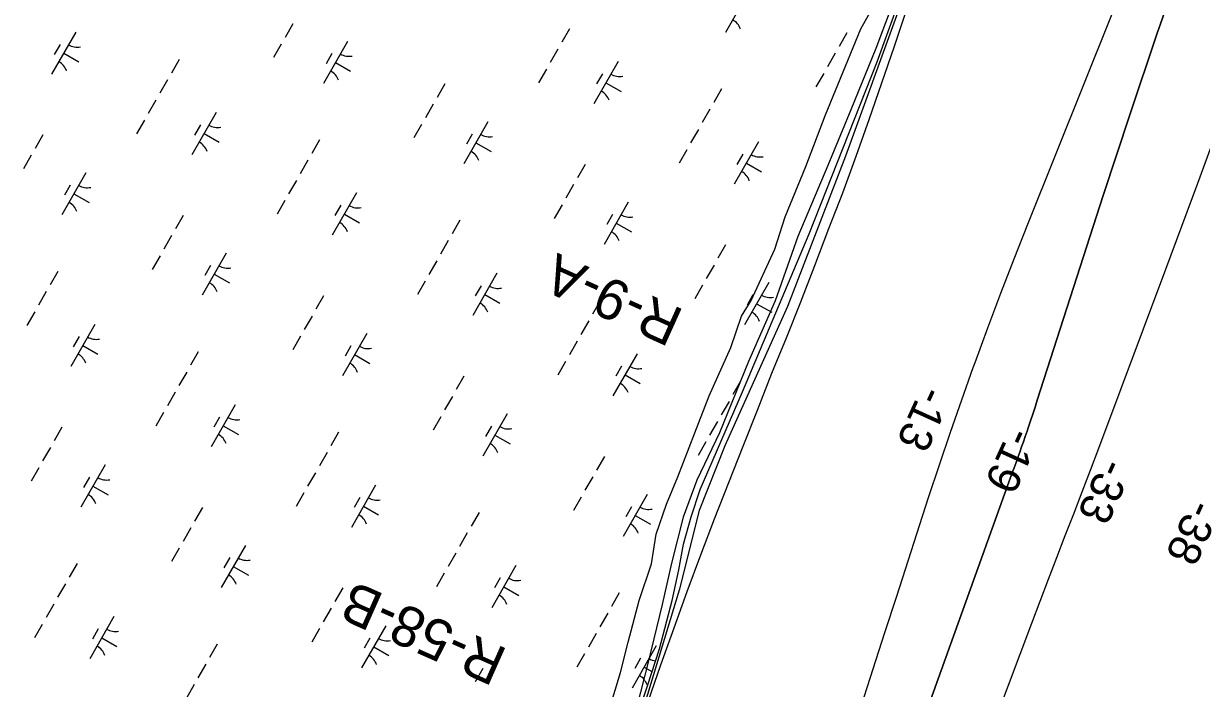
# Model space of a CAD drawing. Extents: x 3930721 to 3950824, y 220441 to 242861.
# Drawn here: x 3941236 to 3942447, y 236510 to 237194 of the extents above; entities that cross this region are included whole.
import ezdxf

# ---------------------------------------------------------------- set-up
doc = ezdxf.new("R2010")
doc.units = 0
for name, color, linetype in [('V-RIVR-EDGE', 7, 'Continuous'), ('V-RIVR-JETY', 7, 'Continuous'), ('V-RIVR-RANG', 7, 'Continuous'), ('V-RIVR-RANG-IDEN', 7, 'Continuous'), ('V-RRAP-FSHR', 7, 'Continuous'), ('V-TOPO-DPTH', 7, 'Continuous'), ('V-TOPO-MINR', 7, 'Continuous'), ('V-WETL-SWMP', 7, 'Continuous')]:
    doc.layers.add(name, color=color, linetype=linetype)

msp = doc.modelspace()

# ---------------------------------------------------------------- linework, layer by layer
at = {"layer": 'V-RIVR-EDGE'}
msp.add_lwpolyline([(3942388.1, 237996.2), (3942359.5, 237893.9), (3942342.1, 237826.3), (3942313.4, 237743.4), (3942293.9, 237654.3), (3942254, 237535.6), (3942177.2, 237310.3), (3942136.3, 237209), (3942081, 237057.5), (3942021.6, 236902.9), (3941957.1, 236759.6), (3941930.5, 236693), (3941910.1, 236611.1), (3941859.9, 236446.3), (3941820, 236338.8), (3941781.1, 236206.8), (3941767.8, 236152.5), (3941755.5, 236064.5), (3941743.2, 235978.5), (3941712.5, 235887.4)], dxfattribs=at)
at = {"layer": 'V-RIVR-JETY'}
for points in [[(3942143, 237250.4), (3942112.2, 237167.9), (3942086.7, 237105), (3942062.9, 237047.8), (3942032.2, 236974.8), (3942008.7, 236908.6), (3941981.3, 236846.1), (3941951.4, 236773), (3941928.1, 236724.4), (3941914.3, 236686.3), (3941902.3, 236638.8), (3941892.4, 236596.3), (3941878.3, 236537.1), (3941866.4, 236491.5)], [(3941881.6, 236638.3), (3941886.3, 236668.7), (3941896.9, 236699.5), (3941908.6, 236727.8), (3941926, 236772.9), (3941940.9, 236811), (3941963.1, 236860.8), (3941974.1, 236892.7), (3941984.1, 236909), (3942008.6, 236961.8), (3942019.2, 236994.9), (3942040.2, 237046.6), (3942060.5, 237099.8), (3942081.1, 237150), (3942096.8, 237188.1), (3942114, 237219.1)], [(3941676.9, 235877.7), (3941691.2, 235925.6), (3941703.5, 235971.9), (3941714.2, 236010.5), (3941724.6, 236055.3), (3941731.2, 236083.7), (3941739.2, 236125.1), (3941750.1, 236182.8), (3941761.7, 236235), (3941770.9, 236278.2), (3941782.3, 236311.7), (3941798, 236349.8), (3941807.8, 236376.6), (3941812.4, 236401.6), (3941819, 236430.4), (3941827.1, 236451.4), (3941838.6, 236490.3), (3941849.6, 236526.5), (3941857.5, 236557.7), (3941869, 236600.6), (3941881.6, 236638.3)]]:
    msp.add_lwpolyline(points, dxfattribs=at)
at = {"layer": 'V-RRAP-FSHR'}
msp.add_lwpolyline([(3942144, 237208.1), (3942131.1, 237170.2), (3942118.2, 237132.4), (3942105.2, 237094.6), (3942091.8, 237056.9), (3942077.9, 237019.4), (3942063.6, 236982.5), (3942049.3, 236944.6), (3942034.8, 236907.4), (3942020, 236870.2), (3942005.1, 236833.8), (3941990.3, 236795.9), (3941975.5, 236758.8), (3941960.8, 236721.6), (3941946.2, 236684.3), (3941931.9, 236647), (3941918, 236609.5), (3941904.7, 236572), (3941891, 236534.2), (3941877.9, 236496.4)], dxfattribs=at)
at = {"layer": 'V-TOPO-DPTH'}
for points in [[(3942128.9, 236387.3), (3942252.6, 236731.7), (3942254.6, 236737), (3942256.5, 236742.4), (3942258.4, 236747.7), (3942260.3, 236753), (3942262.2, 236758.4), (3942264.1, 236763.8), (3942266, 236769.1), (3942267.8, 236774.5), (3942269, 236778), (3942271.3, 236785.1), (3942273.7, 236792.2), (3942276, 236799.4), (3942278.3, 236806.5), (3942346.2, 237016.9), (3942373.5, 237100), (3942401.4, 237182.8), (3942430.3, 237265.4)], [(3942475.6, 237118.1), (3942443, 237029.4), (3942410.1, 236940.9), (3942341.2, 236756.8), (3942332.7, 236734.3), (3942324.1, 236711.8), (3942315.5, 236689.3), (3942306.8, 236666.9), (3942298.1, 236644.4), (3942289.5, 236622), (3942280.9, 236599.5), (3942272.4, 236576.9), (3942188.3, 236353.9), (3942183.6, 236341.1), (3942178.8, 236328.2), (3942174.2, 236315.3), (3942169.6, 236302.4), (3941781.7, 235197.5)], [(3942475.6, 237118.1), (3942443, 237029.4), (3942410.1, 236940.9), (3942341.2, 236756.8), (3942332.7, 236734.3), (3942324.1, 236711.8), (3942315.5, 236689.3), (3942306.8, 236666.9), (3942298.1, 236644.4), (3942289.5, 236622), (3942280.9, 236599.5), (3942272.4, 236576.9), (3942188.3, 236353.9), (3942183.6, 236341.1), (3942178.8, 236328.2), (3942174.2, 236315.3), (3942169.6, 236302.4), (3941781.7, 235197.5)]]:
    msp.add_lwpolyline(points, dxfattribs=at)
at = {"layer": 'V-TOPO-MINR'}
for points in [[(3942411.8, 237345.4), (3942268.2, 236987), (3942254.2, 236951.6), (3942240.5, 236916.1), (3942227.1, 236880.5), (3942214, 236844.8), (3942212.1, 236839.7), (3942200.3, 236806.4), (3942188.6, 236773.1), (3942177.3, 236739.6), (3942166.2, 236706), (3942133.4, 236604.8), (3942121.3, 236567.4), (3942109.2, 236530.1), (3942097.1, 236492.7), (3942085.1, 236455.3), (3942078.2, 236434.1), (3942069.6, 236407.3), (3942061.1, 236380.5), (3942052.7, 236353.7), (3942044.3, 236326.9), (3941811.1, 235576.1)], [(3942430.3, 237265.4), (3942401.4, 237182.8), (3942373.5, 237100), (3942346.2, 237016.9), (3942278.3, 236806.5), (3942276, 236799.4), (3942273.7, 236792.2), (3942271.3, 236785.1), (3942269, 236778), (3942267.8, 236774.5), (3942266, 236769.1), (3942264.1, 236763.8), (3942262.2, 236758.4), (3942260.3, 236753), (3942258.4, 236747.7), (3942256.5, 236742.4), (3942254.6, 236737), (3942252.6, 236731.7), (3942128.9, 236387.3)], [(3942475.6, 237118.1), (3942443, 237029.4), (3942410.1, 236940.9), (3942341.2, 236756.8), (3942332.7, 236734.3), (3942324.1, 236711.8), (3942315.5, 236689.3), (3942306.8, 236666.9), (3942298.1, 236644.4), (3942289.5, 236622), (3942280.9, 236599.5), (3942272.4, 236576.9), (3942188.3, 236353.9), (3942183.6, 236341.1), (3942178.8, 236328.2), (3942174.2, 236315.3), (3942169.6, 236302.4), (3941781.7, 235197.5)]]:
    msp.add_lwpolyline(points, dxfattribs=at)
at = {"layer": 'V-WETL-SWMP'}
for p, q in [((3942113.8, 237154.5), (3942195, 237379.2)), ((3941982.4, 237227.8), (3941957.6, 237184.5)), ((3941512.8, 237193.4), (3941504.9, 237179.5)), ((3941289.5, 237184.9), (3941264.6, 237141.5)), ((3941797.3, 237188.3), (3941789.4, 237174.4)), ((3942082.5, 237184), (3942074.6, 237170.1)), ((3941273.4, 237172.2), (3941267.4, 237161.8)), ((3941500.9, 237172.6), (3941493, 237158.7)), ((3941569, 237175.4), (3941544.2, 237132)), ((3941785.4, 237167.5), (3941777.5, 237153.6)), ((3941277.1, 237163.2), (3941292.7, 237154.2)), ((3941395.9, 237156.7), (3941387.9, 237142.8)), ((3941552.9, 237162.8), (3941546.9, 237152.3)), ((3942070.6, 237163.2), (3942062.6, 237149.3)), ((3941556.6, 237153.7), (3941572.2, 237144.8)), ((3941773.5, 237146.7), (3941765.5, 237132.8)), ((3941847.2, 237154.6), (3941822.4, 237111.3)), ((3942043.7, 236977.6), (3942113.8, 237154.5)), ((3941383.9, 237135.9), (3941376, 237122)), ((3941669.1, 237131.6), (3941661.2, 237117.7)), ((3941831.1, 237142), (3941825.1, 237131.6)), ((3941834.8, 237132.9), (3941850.4, 237124)), ((3942058.7, 237142.4), (3942050.7, 237128.5)), ((3941953.6, 237126.5), (3941945.7, 237112.6)), ((3941372, 237115), (3941364.1, 237101.2)), ((3941657.2, 237110.8), (3941649.2, 237096.9)), ((3941433.8, 237102.2), (3941409, 237058.8)), ((3941941.7, 237105.6), (3941933.7, 237091.8)), ((3941360.1, 237094.2), (3941352.1, 237080.3)), ((3941417.7, 237089.5), (3941411.7, 237079.1)), ((3941645.2, 237089.9), (3941637.3, 237076.1)), ((3941713.4, 237092.7), (3941688.5, 237049.4)), ((3941929.8, 237084.8), (3941921.8, 237070.9)), ((3941255.7, 237079.2), (3941247.8, 237065.3)), ((3941421.4, 237080.5), (3941437, 237071.6)), ((3941540.2, 237074), (3941532.3, 237060.2)), ((3941697.2, 237080.1), (3941691.3, 237069.7)), ((3941700.9, 237071.1), (3941716.6, 237062.1)), ((3941991.6, 237072), (3941966.7, 237028.6)), ((3941243.8, 237058.3), (3941235.8, 237044.4)), ((3941917.8, 237064), (3941909.9, 237050.1)), ((3941975.4, 237059.3), (3941969.5, 237048.9)), ((3941528.3, 237053.2), (3941520.3, 237039.3)), ((3941813.4, 237048.9), (3941805.5, 237035)), ((3941979.2, 237050.3), (3941994.8, 237041.3)), ((3941300, 237040.3), (3941275.1, 236996.9)), ((3941283.8, 237027.7), (3941277.9, 237017.2)), ((3941516.4, 237032.4), (3941508.4, 237018.5)), ((3941801.5, 237028.1), (3941793.6, 237014.2)), ((3941287.5, 237018.6), (3941303.2, 237009.7)), ((3941504.4, 237011.6), (3941496.5, 236997.7)), ((3941578.2, 237019.5), (3941553.3, 236976.1)), ((3941857.7, 237010.1), (3941832.9, 236966.7)), ((3941562, 237006.9), (3941556.1, 236996.5)), ((3941565.8, 236997.8), (3941581.4, 236988.9)), ((3941789.6, 237007.3), (3941781.6, 236993.4)), ((3941400, 236996.5), (3941392.1, 236982.6)), ((3941684.5, 236991.4), (3941676.6, 236977.5)), ((3941841.6, 236997.4), (3941835.6, 236987)), ((3941845.3, 236988.4), (3941860.9, 236979.4)), ((3941388.1, 236975.7), (3941380.2, 236961.8)), ((3941975.2, 236815.2), (3942043.7, 236977.6)), ((3941672.6, 236970.5), (3941664.7, 236956.7)), ((3941957.8, 236966.3), (3941949.8, 236952.4)), ((3941376.2, 236954.8), (3941368.2, 236940.9)), ((3941444.3, 236957.6), (3941419.5, 236914.3)), ((3941660.7, 236949.7), (3941652.7, 236935.8)), ((3941271.1, 236938.9), (3941263.2, 236925)), ((3941428.2, 236945), (3941422.2, 236934.6)), ((3941945.9, 236945.4), (3941937.9, 236931.5)), ((3941431.9, 236936), (3941447.5, 236927)), ((3941648.8, 236928.9), (3941640.8, 236915)), ((3941722.5, 236936.9), (3941697.7, 236893.5)), ((3942002.1, 236927.4), (3941977.2, 236884)), ((3941259.2, 236918.1), (3941251.3, 236904.2)), ((3941544.4, 236913.8), (3941536.4, 236899.9)), ((3941706.4, 236924.2), (3941700.4, 236913.8)), ((3941710.1, 236915.2), (3941725.7, 236906.2)), ((3941933.9, 236924.6), (3941926, 236910.7)), ((3941985.9, 236914.8), (3941980, 236904.3)), ((3941828.9, 236908.7), (3941820.9, 236894.8)), ((3941989.6, 236905.7), (3942005.2, 236896.8)), ((3941247.3, 236897.3), (3941239.3, 236883.4)), ((3941532.5, 236893), (3941524.5, 236879.1)), ((3941309.1, 236884.4), (3941284.3, 236841)), ((3941817, 236887.9), (3941809, 236874)), ((3941293, 236871.8), (3941287, 236861.4)), ((3941520.5, 236872.2), (3941512.6, 236858.3)), ((3941588.7, 236875), (3941563.8, 236831.6)), ((3941805, 236867.1), (3941797.1, 236853.2)), ((3941296.7, 236862.7), (3941312.3, 236853.8)), ((3941415.5, 236856.3), (3941407.5, 236842.4)), ((3941572.5, 236862.3), (3941566.6, 236851.9)), ((3941576.2, 236853.3), (3941591.8, 236844.3)), ((3941866.9, 236854.2), (3941842, 236810.8)), ((3941793.1, 236846.2), (3941785.2, 236832.3)), ((3941850.7, 236841.6), (3941844.8, 236831.1)), ((3941403.6, 236835.4), (3941395.6, 236821.6)), ((3941688.7, 236831.2), (3941680.8, 236817.3)), ((3941854.4, 236832.5), (3941870.1, 236823.6)), ((3941973.2, 236826), (3941965.3, 236812.2)), ((3941391.6, 236814.6), (3941383.7, 236800.7)), ((3941676.8, 236810.3), (3941668.8, 236796.4)), ((3941931.5, 236714.8), (3941975.2, 236815.2)), ((3941961.3, 236805.2), (3941953.4, 236791.3)), ((3941379.7, 236793.8), (3941371.8, 236779.9)), ((3941453.5, 236801.8), (3941428.6, 236758.4)), ((3941733, 236792.3), (3941708.1, 236748.9)), ((3941437.3, 236789.1), (3941431.4, 236778.7)), ((3941441, 236780.1), (3941456.7, 236771.1)), ((3941664.9, 236789.5), (3941656.9, 236775.6)), ((3941716.9, 236779.7), (3941710.9, 236769.2)), ((3941949.4, 236784.4), (3941941.4, 236770.5)), ((3941275.3, 236778.7), (3941267.4, 236764.8)), ((3941559.8, 236773.6), (3941551.9, 236759.7)), ((3941720.6, 236770.6), (3941736.2, 236761.7)), ((3941263.4, 236757.9), (3941255.4, 236744)), ((3941937.4, 236763.6), (3941929.5, 236749.7)), ((3941547.9, 236752.8), (3941540, 236738.9)), ((3941833.1, 236748.5), (3941825.1, 236734.6)), ((3941251.5, 236737.1), (3941243.5, 236723.2)), ((3941319.6, 236739.9), (3941294.7, 236696.5)), ((3941536, 236731.9), (3941528, 236718.1)), ((3941303.5, 236727.2), (3941297.5, 236716.8)), ((3941597.8, 236719.1), (3941573, 236675.7)), ((3941821.1, 236727.7), (3941813.2, 236713.8)), ((3941307.2, 236718.2), (3941322.8, 236709.2)), ((3941524, 236711.1), (3941516.1, 236697.2)), ((3941809.2, 236706.8), (3941801.3, 236692.9)), ((3941877.3, 236709.6), (3941852.5, 236666.3)), ((3941922.3, 236686.7), (3941931.5, 236714.8)), ((3941419.7, 236696), (3941411.7, 236682.2)), ((3941581.7, 236706.4), (3941575.7, 236696)), ((3941585.4, 236697.4), (3941601, 236688.5)), ((3941861.2, 236697), (3941855.2, 236686.6)), ((3941704.2, 236690.9), (3941696.2, 236677.1)), ((3941864.9, 236688), (3941880.5, 236679)), ((3941914.4, 236658.3), (3941922.3, 236686.7)), ((3941407.7, 236675.2), (3941399.8, 236661.3)), ((3941692.2, 236670.1), (3941684.3, 236656.2)), ((3941395.8, 236654.4), (3941387.9, 236640.5)), ((3941463.9, 236657.2), (3941439.1, 236613.8)), ((3941680.3, 236649.3), (3941672.4, 236635.4)), ((3941909.6, 236631.9), (3941914.4, 236658.3)), ((3941290.8, 236638.5), (3941282.8, 236624.6)), ((3941447.8, 236644.6), (3941441.8, 236634.1)), ((3941451.5, 236635.5), (3941467.1, 236626.6)), ((3941742.1, 236636.4), (3941717.3, 236593)), ((3941668.4, 236628.5), (3941660.4, 236614.6)), ((3941726, 236623.8), (3941720, 236613.4)), ((3941902.9, 236600.7), (3941909.6, 236631.9)), ((3941278.8, 236617.7), (3941270.9, 236603.8)), ((3941564, 236613.4), (3941556.1, 236599.5)), ((3941729.7, 236614.7), (3941745.3, 236605.8)), ((3941848.5, 236608.3), (3941840.6, 236594.4)), ((3941889.8, 236550.9), (3941902.9, 236600.7)), ((3941266.9, 236596.8), (3941259, 236583)), ((3941552.1, 236592.6), (3941544.1, 236578.7)), ((3941836.6, 236587.4), (3941828.6, 236573.6)), ((3941255, 236576), (3941247, 236562.1)), ((3941328.7, 236584), (3941303.9, 236540.6)), ((3941608.3, 236574.5), (3941583.4, 236531.2)), ((3941312.6, 236571.3), (3941306.6, 236560.9)), ((3941316.3, 236562.3), (3941331.9, 236553.4)), ((3941540.2, 236571.7), (3941532.2, 236557.8)), ((3941592.1, 236561.9), (3941586.2, 236551.5)), ((3941824.7, 236566.6), (3941816.7, 236552.7)), ((3941435.1, 236555.8), (3941427.2, 236541.9)), ((3941595.9, 236552.8), (3941611.5, 236543.9)), ((3941886.5, 236553.8), (3941861.6, 236510.4)), ((3941877.4, 236512.9), (3941889.8, 236550.9)), ((3941812.7, 236545.8), (3941804.8, 236531.9)), ((3941870.3, 236541.1), (3941864.4, 236530.7)), ((3941423.2, 236535), (3941415.2, 236521.1)), ((3941708.3, 236530.7), (3941700.4, 236516.8)), ((3941874.1, 236532.1), (3941882.1, 236527.5)), ((3941411.3, 236514.2), (3941403.3, 236500.3)), ((3941814.6, 236324.4), (3941877.4, 236512.9))]:
    msp.add_line(p, q, dxfattribs=at)
for centre, start, end in [((3941956.5, 237182.1), 19.4279, 60.9715), ((3941291, 237187), 239.4279, 280.9715), ((3941570.5, 237177.6), 239.4279, 280.9715), ((3941263.5, 237139.1), 19.4279, 60.9715), ((3941543.1, 237129.6), 19.4279, 60.9715), ((3941848.7, 237156.8), 239.4279, 280.9715), ((3941821.3, 237108.9), 19.4279, 60.9715), ((3941435.3, 237104.4), 239.4279, 280.9715), ((3941407.9, 237056.4), 19.4279, 60.9715), ((3941714.9, 237094.9), 239.4279, 280.9715), ((3941687.4, 237047), 19.4279, 60.9715), ((3941993.1, 237074.1), 239.4279, 280.9715), ((3941965.6, 237026.2), 19.4279, 60.9715), ((3941301.5, 237042.5), 239.4279, 280.9715), ((3941274, 236994.5), 19.4279, 60.9715), ((3941579.7, 237021.7), 239.4279, 280.9715), ((3941552.2, 236973.8), 19.4279, 60.9715), ((3941859.2, 237012.2), 239.4279, 280.9715), ((3941831.8, 236964.3), 19.4279, 60.9715), ((3941445.8, 236959.8), 239.4279, 280.9715), ((3941418.4, 236911.9), 19.4279, 60.9715), ((3941724, 236939), 239.4279, 280.9715), ((3942003.6, 236929.6), 239.4279, 280.9715), ((3941696.6, 236891.1), 19.4279, 60.9715), ((3941976.1, 236881.6), 19.4279, 60.9715), ((3941310.6, 236886.6), 239.4279, 280.9715), ((3941283.2, 236838.7), 19.4279, 60.9715), ((3941590.2, 236877.1), 239.4279, 280.9715), ((3941562.7, 236829.2), 19.4279, 60.9715), ((3941868.4, 236856.4), 239.4279, 280.9715), ((3941840.9, 236808.4), 19.4279, 60.9715), ((3941455, 236803.9), 239.4279, 280.9715), ((3941427.5, 236756), 19.4279, 60.9715), ((3941734.5, 236794.5), 239.4279, 280.9715), ((3941707, 236746.5), 19.4279, 60.9715), ((3941321.1, 236742), 239.4279, 280.9715), ((3941293.6, 236694.1), 19.4279, 60.9715), ((3941599.3, 236721.3), 239.4279, 280.9715), ((3941878.8, 236711.8), 239.4279, 280.9715), ((3941571.9, 236673.3), 19.4279, 60.9715), ((3941851.4, 236663.9), 19.4279, 60.9715), ((3941465.4, 236659.4), 239.4279, 280.9715), ((3941438, 236611.4), 19.4279, 60.9715), ((3941743.7, 236638.6), 239.4279, 280.9715), ((3941716.2, 236590.7), 19.4279, 60.9715), ((3941330.2, 236586.2), 239.4279, 280.9715), ((3941609.8, 236576.7), 239.4279, 280.9715), ((3941302.8, 236538.2), 19.4279, 60.9715), ((3941582.3, 236528.8), 19.4279, 60.9715), ((3941888, 236555.9), 239.4279, 262.5969), ((3941860.5, 236508), 19.4279, 60.9715)]:
    msp.add_arc(centre, 17.6, start, end, dxfattribs=at)

# ---------------------------------------------------------------- texts
at = {"layer": 'V-RIVR-RANG'}
for s, p in [('-13', (3942160.1, 236823.1)), ('-19', (3942250.5, 236780.4)), ('-33', (3942346, 236748.7)), ('-38', (3942436.6, 236706.4))]:
    msp.add_text(s, height=33.5, rotation=245.5483, dxfattribs=at).set_placement(p)
at = {"layer": 'V-RIVR-RANG-IDEN'}
for s, rotation, p in [('R-9-A', 155.69, (3941916.6, 236898.6)), ('R-58-B', 156.0487, (3941735.2, 236549.9))]:
    msp.add_text(s, height=41.5, rotation=rotation, dxfattribs=at).set_placement(p)

doc.saveas('drawing.dxf')
